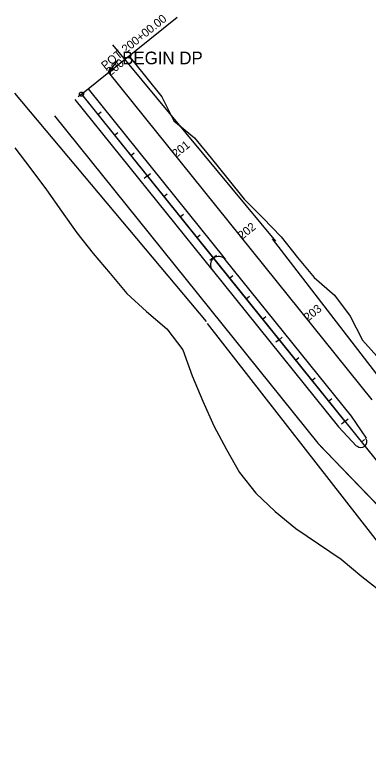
# Model space of a CAD drawing. Extents: x 2717836 to 2719883, y 337327 to 339806.
# Drawn here: x 2717836 to 2718173, y 339108 to 339806 of the extents above; entities that cross this region are included whole.
import ezdxf

# ---------------------------------------------------------------- set-up
doc = ezdxf.new("R2010")
doc.units = 0
for name, color, linetype in [('Level 1', 7, 'Continuous'), ('Level 22', 7, 'Continuous'), ('Level 23', 7, 'Continuous'), ('Level 3', 7, 'Continuous'), ('Level 31', 7, 'Continuous'), ('Level 5', 7, 'Continuous'), ('Level 60', 7, 'Continuous'), ('Level 62', 7, 'Continuous'), ('Level 8', 7, 'Continuous')]:
    doc.layers.add(name, color=color, linetype=linetype)

msp = doc.modelspace()

# ---------------------------------------------------------------- linework, layer by layer
at = {"layer": 'Level 1'}
msp.add_line((2717900.04, 339730.6), (2718401.03, 339107.9), dxfattribs=at)
at = {"layer": 'Level 22'}
for p, q in [((2717945.23, 339766.96), (2717960.9, 339747.48)), ((2717960.9, 339747.48), (2717976.57, 339728)), ((2717976.57, 339728), (2717987.99, 339705.1)), ((2717987.99, 339705.1), (2718007.71, 339688.88)), ((2718007.71, 339688.88), (2718023.59, 339669.57)), ((2717836.67, 339679.61), (2717851.67, 339659.6)), ((2718023.59, 339669.57), (2718039.26, 339650.09)), ((2717851.67, 339659.6), (2717866.61, 339639.53)), ((2718039.26, 339650.09), (2718054.93, 339630.61)), ((2717866.61, 339639.53), (2717881.03, 339619.05)), ((2718054.93, 339630.61), (2718072.59, 339612.73)), ((2717881.03, 339619.05), (2717895.6, 339598.68)), ((2718072.59, 339612.73), (2718090.16, 339594.78)), ((2717895.6, 339598.68), (2717911.02, 339579)), ((2718090.16, 339594.78), (2718105.6, 339575.11)), ((2717911.02, 339579), (2717927.26, 339559.98)), ((2718105.6, 339575.11), (2718121.64, 339555.93)), ((2717927.26, 339559.98), (2717943.25, 339540.76)), ((2718121.64, 339555.93), (2718140.93, 339539.36)), ((2717943.25, 339540.76), (2717961.83, 339523.62)), ((2718140.93, 339539.36), (2718155.89, 339519.32)), ((2717961.83, 339523.62), (2717981.21, 339507.13)), ((2718155.89, 339519.32), (2718167.42, 339496.5)), ((2717981.21, 339507.13), (2717996.41, 339487.27)), ((2718167.42, 339496.5), (2718184.11, 339477.85)), ((2717996.41, 339487.27), (2718005.51, 339462.5)), ((2718005.51, 339462.5), (2718015.51, 339438.46)), ((2718015.51, 339438.46), (2718025.92, 339414.75)), ((2718025.92, 339414.75), (2718038.12, 339392.48)), ((2718038.12, 339392.48), (2718050.55, 339370.39)), ((2718050.55, 339370.39), (2718065.89, 339350.65)), ((2718065.89, 339350.65), (2718084.42, 339333.47)), ((2718084.42, 339333.47), (2718104.05, 339317.18)), ((2718104.05, 339317.18), (2718125.67, 339302.48)), ((2718125.67, 339302.48), (2718147.31, 339287.81)), ((2718147.31, 339287.81), (2718166.86, 339271.45)), ((2718166.86, 339271.45), (2718187.13, 339255.67))]:
    msp.add_line(p, q, dxfattribs=at)
at = {"layer": 'Level 23'}
for p, q in [((2718085.16, 339590.77), (2717929.82, 339777.44)), ((2718018.9, 339514.3), (2717836.44, 339731.4)), ((2718222.31, 339410.32), (2718081.98, 339592.89)), ((2718281.94, 339176.11), (2718019.96, 339512.18))]:
    msp.add_line(p, q, dxfattribs=at)
at = {"layer": 'Level 3'}
for p, q in [((2717925.75, 339751.29), (2718176.49, 339439.63)), ((2717906.28, 339735.62), (2718036.66, 339573.55)), ((2717893.81, 339725.59), (2718024.19, 339563.53)), ((2717874.33, 339709.91), (2718125.07, 339398.26))]:
    msp.add_line(p, q, dxfattribs=at)
for points in [[(2718125.07, 339398.26), (2718125.54, 339397.77), (2718126.01, 339397.28), (2718126.48, 339396.79), (2718126.95, 339396.31), (2718127.43, 339395.82), (2718127.89, 339395.33), (2718128.37, 339394.84), (2718128.84, 339394.35), (2718129.31, 339393.86), (2718129.78, 339393.37), (2718130.25, 339392.89), (2718130.72, 339392.4), (2718131.19, 339391.91), (2718131.66, 339391.42), (2718132.14, 339390.93), (2718132.6, 339390.45), (2718133.08, 339389.95), (2718133.55, 339389.47), (2718134.02, 339388.98), (2718134.49, 339388.5), (2718134.96, 339388), (2718135.43, 339387.52), (2718135.9, 339387.03), (2718136.37, 339386.54), (2718136.84, 339386.05), (2718137.32, 339385.56), (2718137.78, 339385.08), (2718138.26, 339384.58), (2718138.72, 339384.1), (2718139.2, 339383.61), (2718139.67, 339383.12), (2718140.14, 339382.63), (2718140.61, 339382.14), (2718141.08, 339381.66), (2718141.55, 339381.17), (2718142.02, 339380.68), (2718142.49, 339380.19), (2718142.97, 339379.7), (2718143.44, 339379.22), (2718143.91, 339378.72), (2718144.38, 339378.24), (2718144.85, 339377.75), (2718145.32, 339377.26), (2718145.79, 339376.77), (2718146.26, 339376.28), (2718146.73, 339375.8), (2718147.21, 339375.31), (2718147.67, 339374.82), (2718148.15, 339374.33), (2718148.61, 339373.85), (2718149.09, 339373.35), (2718149.56, 339372.86), (2718150.03, 339372.38), (2718150.5, 339371.89), (2718150.97, 339371.4), (2718151.44, 339370.91), (2718151.91, 339370.43), (2718152.38, 339369.94), (2718152.85, 339369.45), (2718153.33, 339368.96), (2718153.8, 339368.47), (2718154.27, 339367.98), (2718154.74, 339367.49), (2718155.21, 339367.01), (2718155.68, 339366.52), (2718156.15, 339366.03), (2718156.62, 339365.54), (2718157.1, 339365.05), (2718157.56, 339364.57), (2718158.04, 339364.07), (2718158.5, 339363.59), (2718158.98, 339363.1), (2718159.45, 339362.61), (2718159.92, 339362.12)], [(2718159.92, 339362.12), (2718160.39, 339361.63), (2718160.86, 339361.15), (2718161.33, 339360.66), (2718161.8, 339360.17), (2718162.27, 339359.68), (2718162.74, 339359.2), (2718163.22, 339358.7), (2718163.69, 339358.21), (2718164.16, 339357.73), (2718164.63, 339357.24), (2718165.1, 339356.75), (2718165.57, 339356.26), (2718166.04, 339355.78), (2718166.51, 339355.29), (2718166.99, 339354.79), (2718167.45, 339354.31), (2718167.93, 339353.82), (2718168.39, 339353.33), (2718168.87, 339352.84), (2718169.34, 339352.36), (2718169.81, 339351.87), (2718170.28, 339351.38), (2718170.75, 339350.89), (2718171.22, 339350.4), (2718171.69, 339349.92), (2718172.16, 339349.42), (2718172.63, 339348.94), (2718173.11, 339348.45), (2718173.57, 339347.96), (2718174.05, 339347.47), (2718174.52, 339346.98), (2718174.99, 339346.5), (2718175.46, 339346.01), (2718175.93, 339345.52), (2718176.4, 339345.03), (2718176.87, 339344.55), (2718177.34, 339344.05), (2718177.82, 339343.56), (2718178.28, 339343.08), (2718178.76, 339342.59), (2718179.23, 339342.1), (2718179.7, 339341.61), (2718180.17, 339341.13), (2718180.64, 339340.64), (2718181.11, 339340.14), (2718181.58, 339339.66), (2718182.05, 339339.17), (2718182.52, 339338.68), (2718183, 339338.19), (2718183.46, 339337.71), (2718183.94, 339337.22), (2718184.41, 339336.73), (2718184.88, 339336.24), (2718185.35, 339335.75), (2718185.82, 339335.27), (2718186.29, 339334.77), (2718186.76, 339334.29), (2718187.23, 339333.8), (2718187.7, 339333.32), (2718188.17, 339332.82), (2718188.65, 339332.33), (2718189.12, 339331.85), (2718189.59, 339331.36), (2718190.06, 339330.87), (2718190.53, 339330.38), (2718191, 339329.9), (2718191.47, 339329.41), (2718191.94, 339328.91), (2718192.41, 339328.43), (2718192.89, 339327.94), (2718193.35, 339327.45), (2718193.83, 339326.96), (2718194.77, 339325.99)]]:
    msp.add_spline(points, degree=3, dxfattribs=at)
at = {"layer": 'Level 31'}
for p, q in [((2717901.6, 339731.85), (2717991.22, 339803.96)), ((2717900.04, 339730.6), (2717903.16, 339733.11)), ((2717900.04, 339730.6), (2717896.93, 339728.09)), ((2717915.71, 339711.12), (2717918.83, 339713.63)), ((2717931.38, 339691.64), (2717934.5, 339694.15)), ((2717947.06, 339672.17), (2717950.17, 339674.67)), ((2717962.73, 339652.69), (2717959.61, 339650.18)), ((2717962.73, 339652.69), (2717965.84, 339655.19)), ((2717978.4, 339633.21), (2717981.51, 339635.72)), ((2717994.07, 339613.73), (2717997.19, 339616.24)), ((2718009.74, 339594.25), (2718012.86, 339596.76)), ((2718025.41, 339574.77), (2718022.3, 339572.27)), ((2718025.41, 339574.77), (2718028.53, 339577.28)), ((2718041.08, 339555.29), (2718044.2, 339557.8)), ((2718056.75, 339535.82), (2718059.87, 339538.32)), ((2718072.43, 339516.34), (2718075.54, 339518.84)), ((2718088.1, 339496.86), (2718084.98, 339494.35)), ((2718088.1, 339496.86), (2718091.21, 339499.37)), ((2718103.77, 339477.38), (2718106.88, 339479.89)), ((2718119.44, 339457.9), (2718122.56, 339460.41)), ((2718135.11, 339438.42), (2718138.23, 339440.93)), ((2718150.78, 339418.94), (2718147.67, 339416.44)), ((2718150.78, 339418.94), (2718153.9, 339421.45)), ((2718166.45, 339399.47), (2718169.57, 339401.97))]:
    msp.add_line(p, q, dxfattribs=at)
msp.add_circle((2717900.04, 339730.6), 2, dxfattribs=at)
at = {"layer": 'Level 5'}
for p, q in [((2718157.02, 339423.96), (2718036.92, 339573.23)), ((2718024.45, 339563.2), (2718144.55, 339413.93)), ((2718171.27, 339403.02), (2718157.02, 339423.96)), ((2718144.55, 339413.93), (2718161.94, 339395.54))]:
    msp.add_line(p, q, dxfattribs=at)
for centre, radius, start, end in [((2718030.72, 339568.17), 8, 39.29609, 218.34012), ((2718166.29, 339399.67), 5.5, 223.33628, 34.24903)]:
    msp.add_arc(centre, radius, start, end, dxfattribs=at)
at = {"layer": 'Level 62'}
for q in [(2717935.07, 339763.14), (2717927.65, 339756.43), (2717930.91, 339754.26)]:
    msp.add_line((2717925.75, 339751.29), q, dxfattribs=at)
at = {"layer": 'Level 8'}
for p, q in [((2717900.04, 339730.6), (2718042.66, 339553.34)), ((2718042.66, 339553.34), (2718150.78, 339418.94))]:
    msp.add_line(p, q, dxfattribs=at)

# ---------------------------------------------------------------- texts
at = {"layer": 'Level 31'}
for s, p in [('POT 200+00.00', (2717922.78, 339753.39)), ('200', (2717927.48, 339747.54)), ('201', (2717990.17, 339669.63)), ('202', (2718052.85, 339591.72)), ('203', (2718115.54, 339513.8))]:
    msp.add_text(s, height=8, rotation=38.81809, dxfattribs=at).set_placement(p)
at = {"layer": 'Level 60'}
msp.add_text('BEGIN DP', height=12, dxfattribs=at).set_placement((2717938.76, 339759.02))

doc.saveas('drawing.dxf')
